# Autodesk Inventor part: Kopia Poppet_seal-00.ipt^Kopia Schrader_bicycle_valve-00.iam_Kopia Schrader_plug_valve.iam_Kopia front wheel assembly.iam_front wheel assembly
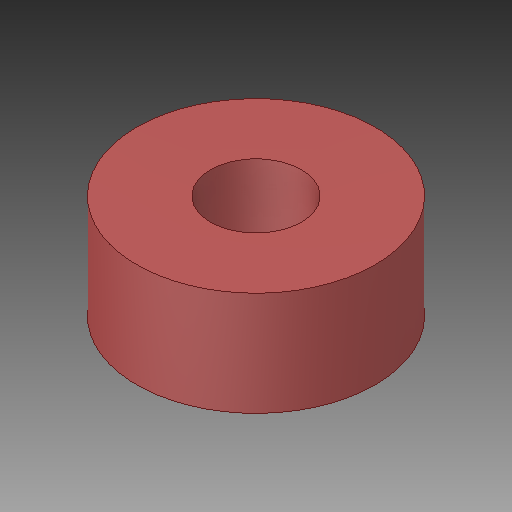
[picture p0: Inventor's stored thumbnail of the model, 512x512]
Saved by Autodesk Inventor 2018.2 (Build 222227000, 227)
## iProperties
Created: 2017-09
Part Number: Kopia Poppet_seal-00.ipt^Kopia Schrader_bicycle_valve-00.iam_Kopia Schrader_plug_valve.iam_Kopia front wheel assembly.iam_front wheel assembly
Material: Ogólny
Document SubType Name: Modeling
Designer: Tomasz
Density: 1 g/cm^3
Appearance: Domyślna
Author: Tomasz
Sending System: SolidWorks 2017
Last Author: Tomasz
Last Saved: 2017-09-11
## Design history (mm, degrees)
feature "Poppet_seal-00.ipt"
node "Bryła1"
